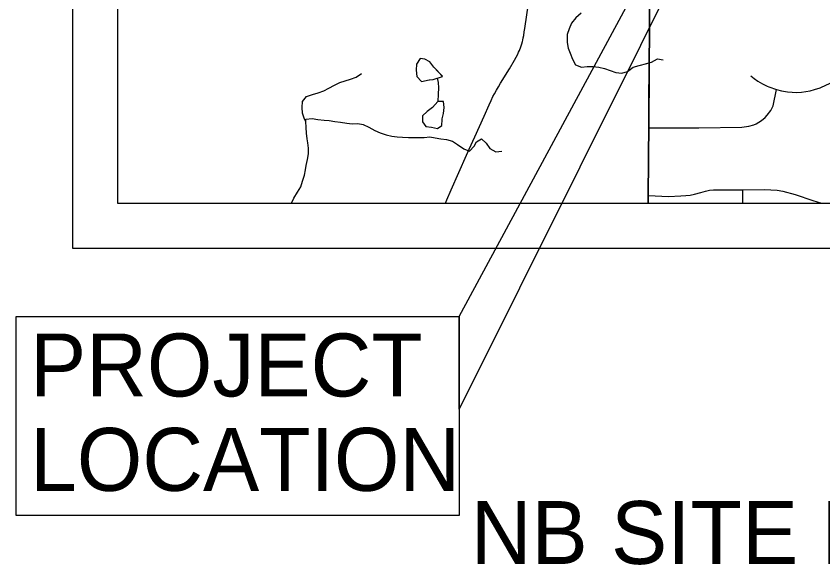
# Model space of a CAD drawing. Extents: x 0 to 34, y 0 to 22.
# Drawn here: x 1.875 to 3.669, y 13.295 to 14.516 of the extents above; entities that cross this region are included whole.
import ezdxf

# ---------------------------------------------------------------- set-up
doc = ezdxf.new("R2010")
doc.units = 0
for name, color, linetype in [('Default', 7, 'Continuous'), ('GM_X_County_Road', 7, 'Continuous'), ('GM_X_Minor_Lake', 7, 'Continuous'), ('GM_X_Minor_River', 7, 'Continuous'), ('GM_X_Township_Road', 7, 'Continuous'), ('SH_Cut_Line', 7, 'Continuous'), ('SH_Data', 7, 'Continuous'), ('SH_Text', 7, 'Continuous')]:
    doc.layers.add(name, color=color, linetype=linetype)

msp = doc.modelspace()

# ---------------------------------------------------------------- linework, layer by layer
at = {"layer": 'Default'}
msp.add_lwpolyline([(3.2815, 15.7537), (3.2811, 15.7294), (3.2832, 14.8896), (3.2841, 14.501), (3.2822, 14.2781), (3.2808, 14.1155), (3.2807, 14.1), (8.4439, 14.1), (8.4391, 14.4529), (8.4328, 14.555), (8.4328, 14.5554), (8.4608, 15.4787), (8.4608, 15.9241)], dxfattribs=at)
msp.add_lwpolyline([(2.1, 15.8248), (2.1, 14.1), (3.2807, 14.1), (3.2808, 14.1155), (3.2822, 14.2781), (3.2841, 14.501), (3.2832, 14.8896), (3.2811, 15.7294), (3.2815, 15.7537), (3.2829, 15.8433)], close=True, dxfattribs=at)
at = {"layer": 'GM_X_County_Road'}
for points in [[(3.2821, 14.2674), (3.2822, 14.2949), (3.2824, 14.3323), (3.2833, 14.397), (3.2836, 14.4329), (3.2838, 14.4734), (3.2837, 14.5933), (3.2836, 14.6255), (3.2837, 14.6664), (3.2838, 14.6736), (3.2838, 14.7095), (3.2841, 14.7456), (3.2841, 14.7863), (3.2839, 14.8273), (3.2837, 14.8684), (3.2841, 14.8751), (3.2852, 14.8808), (3.2868, 14.8852), (3.2894, 14.8897)], [(3.2812, 14.1166), (3.2814, 14.1699), (3.2817, 14.204), (3.2819, 14.238), (3.2821, 14.2674)], [(3.2811, 14.1), (3.2811, 14.104), (3.2812, 14.1103), (3.2812, 14.1166)]]:
    msp.add_lwpolyline(points, dxfattribs=at)
at = {"layer": 'GM_X_Minor_Lake'}
for points in [[(2.8233, 14.3818), (2.8041, 14.4024), (2.7953, 14.4146), (2.7839, 14.4203), (2.7736, 14.4214), (2.7653, 14.4092), (2.7645, 14.3956), (2.7661, 14.3819), (2.7768, 14.3705), (2.7934, 14.374), (2.794, 14.3742)], [(2.8231, 14.3821), (2.8041, 14.4024), (2.7953, 14.4146), (2.7839, 14.4203), (2.7736, 14.4214), (2.7653, 14.4092), (2.7645, 14.3956), (2.7661, 14.3819), (2.7768, 14.3705), (2.7934, 14.374), (2.7939, 14.3741)], [(2.7938, 14.3742), (2.8026, 14.3747), (2.8232, 14.3818)], [(2.794, 14.3742), (2.8026, 14.3747), (2.8233, 14.3818)], [(2.8126, 14.3257), (2.8012, 14.3127), (2.789, 14.3036), (2.7788, 14.2944), (2.7784, 14.2807), (2.7864, 14.2701), (2.7986, 14.2686), (2.8119, 14.2663), (2.8218, 14.2724), (2.8225, 14.2861), (2.8228, 14.2874)], [(2.8126, 14.3257), (2.8012, 14.3127), (2.789, 14.3036), (2.7788, 14.2944), (2.7784, 14.2807), (2.7864, 14.2701), (2.7986, 14.2686), (2.8119, 14.2663), (2.8218, 14.2724), (2.8225, 14.2861), (2.8228, 14.2874)], [(2.8228, 14.2874), (2.8252, 14.299), (2.8267, 14.3127), (2.8251, 14.3257), (2.8126, 14.3257)], [(2.8227, 14.2871), (2.8252, 14.299), (2.8267, 14.3127), (2.8251, 14.3257), (2.8126, 14.3257)]]:
    msp.add_lwpolyline(points, dxfattribs=at)
at = {"layer": 'GM_X_Minor_River'}
for points in [[(3.1319, 14.5223), (3.1201, 14.5124), (3.1103, 14.5006), (3.1049, 14.488), (3.1004, 14.4751), (3.1004, 14.4618), (3.1008, 14.4576), (3.1027, 14.4446), (3.1073, 14.4332), (3.1127, 14.4203), (3.1191, 14.4078), (3.1328, 14.4025), (3.145, 14.4036), (3.158, 14.4037), (3.1709, 14.4021), (3.1838, 14.3995), (3.1964, 14.3953), (3.209, 14.3904), (3.2219, 14.3889), (3.2345, 14.3927), (3.2474, 14.4022), (3.2611, 14.4061), (3.2775, 14.4106)], [(3.2774, 14.4105), (3.2884, 14.4136), (3.3012, 14.4209), (3.3141, 14.4184)], [(2.5189, 14.2816), (2.5159, 14.2865), (2.512, 14.3002), (2.5109, 14.3123), (2.5116, 14.326), (2.5204, 14.3375), (2.534, 14.3417), (2.5462, 14.3455), (2.5588, 14.3501), (2.5702, 14.3558), (2.5827, 14.3622), (2.5945, 14.3683), (2.6067, 14.3718), (2.6185, 14.3756), (2.631, 14.3802), (2.6432, 14.3886)], [(2.8112, 14.3777), (2.8132, 14.368), (2.814, 14.3562), (2.8137, 14.3425), (2.813, 14.3257)], [(2.5189, 14.2816), (2.5193, 14.2865), (2.533, 14.2884), (2.5459, 14.2862), (2.5596, 14.2847), (2.571, 14.2835), (2.5836, 14.2816), (2.5965, 14.2801), (2.6102, 14.2779), (2.622, 14.2767), (2.635, 14.2768), (2.6468, 14.2745), (2.659, 14.2688), (2.6727, 14.2616), (2.6848, 14.2563), (2.6978, 14.2517), (2.7103, 14.2491), (2.7221, 14.2472), (2.7343, 14.2468), (2.7473, 14.2457), (2.7602, 14.2461), (2.7731, 14.2461), (2.7826, 14.2458), (2.7952, 14.2473), (2.8066, 14.2454), (2.8196, 14.2431), (2.8321, 14.2416), (2.8451, 14.2379), (2.8569, 14.2306), (2.8706, 14.2204), (2.8831, 14.2158), (2.8938, 14.2269), (2.8987, 14.2364), (2.9097, 14.2429), (2.9204, 14.2334), (2.9288, 14.2216), (2.9417, 14.214), (2.9554, 14.2152)], [(2.4874, 14.1), (2.4921, 14.1112), (2.5009, 14.1245), (2.5081, 14.1359), (2.5115, 14.1488), (2.516, 14.1622), (2.5183, 14.1743), (2.5202, 14.1838), (2.5225, 14.1968), (2.5251, 14.2097), (2.5247, 14.2219), (2.5239, 14.2337), (2.5224, 14.2432), (2.5205, 14.2553), (2.5201, 14.2679), (2.5189, 14.2816)]]:
    msp.add_lwpolyline(points, dxfattribs=at)
at = {"layer": 'GM_X_Township_Road'}
msp.add_line((3.4912, 14.1), (3.4912, 14.1298), dxfattribs=at)
for points in [[(2.83, 14.1), (2.8331, 14.1073), (2.8426, 14.1297), (2.8769, 14.2065), (2.8827, 14.2199), (2.8951, 14.2474), (2.9156, 14.2935), (2.9267, 14.3187), (2.9312, 14.3284), (2.9355, 14.3373), (2.9388, 14.3434), (2.9432, 14.3514), (2.9478, 14.359), (2.9525, 14.3665), (2.972, 14.3987), (2.9831, 14.4178), (2.9905, 14.4312), (2.9926, 14.4355), (2.9943, 14.4394), (2.9976, 14.4479), (2.9996, 14.4546), (3.001, 14.4595), (3.0018, 14.4628), (3.0029, 14.4677), (3.0038, 14.4728), (3.005, 14.4809), (3.006, 14.4883), (3.0146, 14.5441)], [(3.5093, 14.3834), (3.5168, 14.3773), (3.5248, 14.3716), (3.5349, 14.3655), (3.5457, 14.36), (3.5495, 14.3583), (3.5662, 14.3524), (3.5774, 14.3496), (3.5905, 14.3474), (3.6014, 14.3465), (3.6102, 14.3464), (3.6221, 14.347), (3.6314, 14.3481), (3.6413, 14.3499), (3.6508, 14.3524), (3.6632, 14.3566), (3.6778, 14.3629), (3.7091, 14.3769), (3.7725, 14.4052)], [(3.2821, 14.2674), (3.3932, 14.2673), (3.4892, 14.269), (3.5048, 14.2708), (3.5157, 14.2743), (3.5208, 14.2764), (3.5328, 14.2837), (3.5413, 14.2906), (3.5458, 14.2954), (3.5534, 14.3058), (3.5586, 14.3162), (3.5662, 14.3524)], [(3.2812, 14.1166), (3.3263, 14.1143), (3.3532, 14.1164), (3.3643, 14.117), (3.374, 14.1176), (3.384, 14.1195), (3.3976, 14.1234), (3.4081, 14.1264), (3.4169, 14.1285), (3.4263, 14.1297), (3.4912, 14.1298), (3.5407, 14.13), (3.554, 14.1297), (3.5676, 14.1285), (3.5803, 14.1264), (3.6075, 14.1188), (3.6471, 14.1059), (3.6662, 14.1)]]:
    msp.add_lwpolyline(points, dxfattribs=at)
at = {"layer": 'SH_Cut_Line'}
for points in [[(3.2826, 20.9), (2.1, 20.9), (2.1, 14.1), (3.2807, 14.1), (3.2808, 14.1155), (3.2822, 14.2781), (3.2841, 14.501), (3.2832, 14.8896), (3.2811, 15.7294), (3.2815, 15.7537), (3.2829, 15.8433), (3.2832, 16.3898), (3.2835, 17.0107), (3.2837, 17.3796), (3.2907, 18.4315), (3.2904, 19.1173), (3.2901, 19.68), (3.2888, 19.8918), (3.2845, 20.5998), (3.2843, 20.6124)], [(3.2807, 14.1), (8.9, 14.1), (8.9, 20.9), (3.2826, 20.9), (3.2843, 20.6124), (3.2845, 20.5998), (3.2888, 19.8918), (3.2901, 19.68), (3.2904, 19.1173), (3.2907, 18.4315), (3.2837, 17.3796), (3.2835, 17.0107), (3.2832, 16.3898), (3.2829, 15.8433), (3.2815, 15.7537), (3.2811, 15.7294), (3.2832, 14.8896), (3.2841, 14.501), (3.2822, 14.2781), (3.2808, 14.1155)]]:
    msp.add_lwpolyline(points, close=True, dxfattribs=at)
at = {"layer": 'SH_Data'}
for p, q in [((2, 21), (2, 14)), ((2.1, 20.9), (2.1, 14.1)), ((2.1, 14.1), (8.9, 14.1)), ((2.1, 14.1), (2.1, 14.1)), ((2, 14), (9, 14))]:
    msp.add_line(p, q, dxfattribs=at)
at = {"layer": 'SH_Text'}
for points in [[(2.8604, 13.8477), (4.2041, 16.3374), (2.8604, 13.6417)], [(1.8746, 13.8477), (2.8604, 13.8477), (2.8604, 13.4049), (1.8746, 13.4049)]]:
    msp.add_lwpolyline(points, close=True, dxfattribs=at)

# ---------------------------------------------------------------- texts
for s, p in [('PROJECT', (1.9055, 13.6698)), ('LOCATION', (1.9055, 13.4598)), ('NB SITE LATITUDE:  41°12\'30" N   LONGITUDE:  81°40\'10" W', (2.8862, 13.2971))]:
    msp.add_text(s, height=0.14, dxfattribs=at).set_placement(p)

doc.saveas('drawing.dxf')
